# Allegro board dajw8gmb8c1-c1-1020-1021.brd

Outline 329.5 x 128.7 mm; copper layers: TOP, SGND, IN1, SVCC, IN2, IN3, SGND1, BOTTOM. Coordinates in mm from the lower left corner of the outline.

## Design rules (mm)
constraint set DEFAULT: min track width 0.102
net group DFP-S6W10-T123B: nets VCCSENSE VSSSENSE
net group T2B: nets USBPLLMON_N USBPLLMON_P
net group DFP-S4(4.5)W4(4.5)-T123B: nets HDMI_CLK_SINK HDMI_DAT_SINK HDMI_SCL HDMI_SDA
net group DFP-S5(4)W5(4: nets VMA_CLKN0 VMA_CLKN1 VMA_CLKP0 VMA_CLKP1 VMA_RDQS0 VMA_RDQS1 VMA_RDQS2 VMA_RDQS3 VMA_RDQS4 VMA_RDQS5 VMA_RDQS6 VMA_RDQS7 VMA_WDQS0 VMA_WDQS1 VMA_WDQS2 VMA_WDQS3 VMA_WDQS4 VMA_WDQS5 VMA_WDQS6 VMA_WDQS7
net group DFP-S5.5(5.5: nets EDP_AUXN EDP_AUXN_R EDP_AUXP EDP_AUXP_R EDP_TXN0 EDP_TXN0_RC EDP_TXN1 EDP_TXN1_RC EDP_TXP0 EDP_TXP0_RC EDP_TXP1 EDP_TXP1_RC INT_HDMI_TXCN INT_HDMI_TXCN_C INT_HDMI_TXCN_L INT_HDMI_TXCN_R INT_HDMI_TXCP INT_HDMI_TXCP_C INT_HDMI_TXCP_L INT_HDMI_TXCP_R INT_HDMI_TXN0 INT_HDMI_TXN0_C INT_HDMI_TXN0_L INT_HDMI_TXN0_R INT_HDMI_TXN1 INT_HDMI_TXN1_C INT_HDMI_TXN1_L INT_HDMI_TXN1_R INT_HDMI_TXN2 INT_HDMI_TXN2_C INT_HDMI_TXN2_L INT_HDMI_TXN2_R INT_HDMI_TXP0 INT_HDMI_TXP0_C INT_HDMI_TXP0_L INT_HDMI_TXP0_R INT_HDMI_TXP1 INT_HDMI_TXP1_C INT_HDMI_TXP1_L INT_HDMI_TXP1_R INT_HDMI_TXP2 INT_HDMI_TXP2_C INT_HDMI_TXP2_L INT_HDMI_TXP2_R M_B_CLKN0 M_B_CLKN1 M_B_CLKP0 M_B_CLKP1 M_B_DQSN0 M_B_DQSN1 M_B_DQSN2 M_B_DQSN3 M_B_DQSN4 M_B_DQSN5 M_B_DQSN6 M_B_DQSN7 M_B_DQSP0 M_B_DQSP1 M_B_DQSP2 M_B_DQSP3 M_B_DQSP4 M_B_DQSP5 M_B_DQSP6 M_B_DQSP7 PCIE_RXN2 PCIE_RXN2_C PCIE_RXN3 PCIE_RXN3_C PCIE_RXN4 PCIE_RXP2 PCIE_RXP2_C PCIE_RXP3 PCIE_RXP3_C PCIE_RXP4 PCIE_TXN2 PCIE_TXN2_C PCIE_TXN3 PCIE_TXN3_C PCIE_TXN4 PCIE_TXN4_C PCIE_TXP2 PCIE_TXP2_C PCIE_TXP3 PCIE_TXP3_C PCIE_TXP4 PCIE_TXP4_C PEG_RXN0 PEG_RXN0_C PEG_RXN1 PEG_RXN1_C PEG_RXN2 PEG_RXN2_C PEG_RXN3 PEG_RXN3_C PEG_RXP0 PEG_RXP0_C PEG_RXP1 PEG_RXP1_C PEG_RXP2 PEG_RXP2_C PEG_RXP3 PEG_RXP3_C PEG_TXN0 PEG_TXN0_C PEG_TXN1 PEG_TXN1_C PEG_TXN2 PEG_TXN2_C PEG_TXN3 PEG_TXN3_C PEG_TXP0 PEG_TXP0_C PEG_TXP1 PEG_TXP1_C PEG_TXP2 PEG_TXP2_C PEG_TXP3 PEG_TXP3_C SATA_RXN1 SATA_RXN1_C SATA_RXP1 SATA_RXP1_C SATA_TXN1 SATA_TXN1_C SATA_TXP1 SATA_TXP1_C USB3.0_RX1+ USB3.0_RX1- USB3.0_RX2+ USB3.0_RX2- USB3.0_RX3+ USB3.0_RX3- USB3.0_TX1+ USB3.0_TX1+_C USB3.0_TX1- USB3.0_TX1-_C USB3.0_TX2+ USB3.0_TX2+_C USB3.0_TX2- USB3.0_TX2-_C USB3.0_TX3+ USB3.0_TX3+_C USB3.0_TX3- USB3.0_TX3-_C USBP0+ USBP0+_C USBP0- USBP0-_C USBP1+ USBP1+_C USBP1+_R USBP1- USBP1-_C USBP1-_R USBP2+ USBP2+_C USBP2- USBP2-_C USBP3+ USBP3+_R_FT USBP3- USBP3-_R_FT USBP4+ USBP4+_CN USBP4- USBP4-_CN USBP5+ USBP5+_TOUCH USBP5- USBP5-_TOUCH USBP6+ USBP6- USBP7+ USBP7+_TSCR USBP7- USBP7-_TSCR
net group DFP-S5.5W4.5-TB: nets EDP_AUXN_C EDP_AUXP_C EDP_TXN0_C EDP_TXN0_R EDP_TXN0_RL EDP_TXN1_C EDP_TXN1_R EDP_TXN1_RL EDP_TXP0_C EDP_TXP0_R EDP_TXP0_RL EDP_TXP1_C EDP_TXP1_R EDP_TXP1_RL
net group DFP-S6(8: nets CLK_PCIE_CR_N CLK_PCIE_CR_P CLK_PCIE_LANN CLK_PCIE_LANP CLK_PCIE_VGAN CLK_PCIE_VGAP CLK_PCIE_WLANN CLK_PCIE_WLANP
net group DFP-S8W3.5-TB: nets LAN_MX0+ LAN_MX0- LAN_MX1+ LAN_MX1- LAN_MX2+ LAN_MX2- LAN_MX3+ LAN_MX3- MDI0+ MDI0- MDI1+ MDI1- MDI2+ MDI2- MDI3+ MDI3-
net group DFP-S8W4-TB: nets RTC_X1 RTC_X2 XTAL24_IN XTAL24_OUT
net group DFP-S10W4(3.5: nets SMB_CLK_ME1 SMB_DATA_ME1 SMB_PCH_CLK SMB_PCH_DAT SMBCLK SMBCLK0 SMBCLK1 SMBCLK3 SMBDAT0 SMBDAT1 SMBDAT3 SMBDATA
net group DFP-S10W10-T123B: nets REM_DIODE1_N REM_DIODE1_P VGA_THERMDN VGA_THERMDP
net group DFP-S20W40-T123B: nets L_SPK+ L_SPK- R_SPK+ R_SPK- SUB_OUT+ SUB_OUT+_L SUB_OUT- SUB_OUT-_L
net group DFP-S40W40-T123B: nets L_SPK+_R L_SPK-_R R_SPK+_R R_SPK-_R
net group T123B: nets +3.3V_RTC_LDO +CARD_3V3 +DCPSUSBYP +LCDVCC +LED_BL +RTC_1 +RTC_2 +RTC_CELL +V1.05DX_MODPHY +V1.05S_APLLOPI +V1.05S_ASATA3PLL +V1.05S_AUSB3PLL +V1.05S_AXCK_DCB +V1.05S_AXCK_LCPLL +V1.05S_VCCST +V3.3DX_CR +V3.3S_1.8S_LPSS_SDIO +VCCIO_OUT +VCCIOA_OUT +VCCRTCEXT CBN CBP COMBOJACK EARP_L EARP_L1 EARP_L2 EARP_R EARP_R1 EARP_R2 EDP_HPD EXT_MIC_2 EXT_MIC_L1 EXT_MIC_R EXT_MIC_R1 N130831290 N130831312 N130831363 N130831369 N130831515 RUN_ENABLE_1 RUN_ENABLE_2 RUN_ENABLE_3 SENSE_A SENSE_COMBO SM_RCOMP_0 SM_RCOMP_1 SM_RCOMP_2 SUS_ENABLE VREFOUT_AL
net group TB: nets EDP_COMP LAN_XTALI LAN_XTALO PCH_OPIRCOMP PCIE_IREF PROC_OPI_COMP SATA_IREF SATA_RCOMP USB_BIAS
net group W4(3.5: nets M_B_DQ0 M_B_DQ1 M_B_DQ2 M_B_DQ3 M_B_DQ4 M_B_DQ5 M_B_DQ6 M_B_DQ7 M_B_DQ8 M_B_DQ9 M_B_DQ10 M_B_DQ11 M_B_DQ12 M_B_DQ13 M_B_DQ14 M_B_DQ15 M_B_DQ16 M_B_DQ17 M_B_DQ18 M_B_DQ19 M_B_DQ20 M_B_DQ21 M_B_DQ22 M_B_DQ23 M_B_DQ24 M_B_DQ25 M_B_DQ26 M_B_DQ27 M_B_DQ28 M_B_DQ29 M_B_DQ30 M_B_DQ31 M_B_DQ32 M_B_DQ33 M_B_DQ34 M_B_DQ35 M_B_DQ36 M_B_DQ37 M_B_DQ38 M_B_DQ39 M_B_DQ40 M_B_DQ41 M_B_DQ42 M_B_DQ43 M_B_DQ44 M_B_DQ45 M_B_DQ46 M_B_DQ47 M_B_DQ48 M_B_DQ49 M_B_DQ50 M_B_DQ51 M_B_DQ52 M_B_DQ53 M_B_DQ54 M_B_DQ55 M_B_DQ56 M_B_DQ57 M_B_DQ58 M_B_DQ59 M_B_DQ60 M_B_DQ61 M_B_DQ62 M_B_DQ63
net group W4(3.5: nets 51622_ALERT# 51622_VCLK 51622_VDIO ACZ_SPKR AMP_BEEP AP_24M AP_I2S_DIN AP_I2S_DOUT BEEP BUF_PLT_RST# DDR3_DRAMRST# DP_UTIL DPWROK_R DSWVRMEN EC_PWROK EC_SPI_CLK EC_SPI_CS0# EC_SPI_CS# EC_SPI_DIN EC_SPI_DO EC_SPI_SI EC_SPI_SLK EC_SPI_SO EC_WAKE# H_CPU_SVIDALRT# H_CPUPWRGD H_PROCHOT# H_PROCHOT_EC HD_SDIN0 HDA_BEEP2 HDA_BITCLK HDA_BITCLK_R HDA_RST# HDA_RST#_R HDA_SDIN0 HDA_SDOUT HDA_SDOUT_R HDA_SYNC HDA_SYNC_R HSPI_CS# HWPG I2C_CK0 I2C_DA0 I2S_BCLK I2S_LRCK_FS IMVP7_PROCHOT# IRQ_SERIRQ LCD_PWM LPC_CLK_0 LPC_CLK_1 LPC_CLK_DEBUG LPC_CLK_EC LPC_LAD0 LPC_LAD1 LPC_LAD2 LPC_LAD3 LPC_LFRAME# N23727870 PCH_INTVRMEN PCH_SPI_CLK PCH_SPI_CS0# PCH_SPI_CS1# PCH_SPI_SI PCH_SPI_SO PCH_THRMTRIP# PCIE_EC_WAKE# PCIE_WAKE#_R PECI_EC PECI_EC_R PLTRST# RSMRST# RTC_RST# SD_CLK SIO_EXT_SCI# SIO_PWRBTN# SIO_RCIN# SIO_SLP_S3# SIO_SLP_S4# SIO_SLP_S5# SIO_WAKE_SCI# SLP_S0# SM_INTRUDER# SMC_EXTSMI_N SPI_CLK SPI_CS# SPI_SI SPI_SO SRTC_RST# SYS_PWROK SYS_SHDN# THERM_ALERT# THERM_STP# VCCST_PWRGD# VCCST_PWRGD_L VR_SVID_ALERT# VR_SVID_CLK VR_SVID_DATA
net group W4(4.5)-T123B: nets INT_HDMI_HP
net group W5(4.5: nets VMA_CMD0 VMA_CMD2 VMA_CMD3 VMA_CMD4 VMA_CMD5 VMA_CMD6 VMA_CMD7 VMA_CMD8 VMA_CMD9 VMA_CMD10 VMA_CMD11 VMA_CMD12 VMA_CMD13 VMA_CMD14 VMA_CMD15 VMA_CMD16 VMA_CMD18 VMA_CMD19 VMA_CMD20 VMA_CMD21 VMA_CMD22 VMA_CMD23 VMA_CMD24 VMA_CMD25 VMA_CMD26 VMA_CMD27 VMA_CMD28 VMA_CMD29 VMA_CMD30 VMA_DM0 VMA_DM1 VMA_DM2 VMA_DM3 VMA_DM4 VMA_DM5 VMA_DM6 VMA_DM7 VMA_DQ0 VMA_DQ1 VMA_DQ2 VMA_DQ3 VMA_DQ4 VMA_DQ5 VMA_DQ6 VMA_DQ7 VMA_DQ8 VMA_DQ9 VMA_DQ10 VMA_DQ11 VMA_DQ12 VMA_DQ13 VMA_DQ14 VMA_DQ15 VMA_DQ16 VMA_DQ17 VMA_DQ18 VMA_DQ19 VMA_DQ20 VMA_DQ21 VMA_DQ22 VMA_DQ23 VMA_DQ24 VMA_DQ25 VMA_DQ26 VMA_DQ27 VMA_DQ28 VMA_DQ29 VMA_DQ30 VMA_DQ31 VMA_DQ32 VMA_DQ33 VMA_DQ34 VMA_DQ35 VMA_DQ36 VMA_DQ37 VMA_DQ38 VMA_DQ39 VMA_DQ40 VMA_DQ41 VMA_DQ42 VMA_DQ43 VMA_DQ44 VMA_DQ45 VMA_DQ46 VMA_DQ47 VMA_DQ48 VMA_DQ49 VMA_DQ50 VMA_DQ51 VMA_DQ52 VMA_DQ53 VMA_DQ54 VMA_DQ55 VMA_DQ56 VMA_DQ57 VMA_DQ58 VMA_DQ59 VMA_DQ60 VMA_DQ61 VMA_DQ62 VMA_DQ63
net group W6.5(5.5: nets M_B_A0 M_B_A1 M_B_A2 M_B_A3 M_B_A4 M_B_A5 M_B_A6 M_B_A7 M_B_A8 M_B_A9 M_B_A10 M_B_A11 M_B_A12 M_B_A13 M_B_A14 M_B_A15 M_B_BS#0 M_B_BS#1 M_B_BS#2 M_B_CAS# M_B_CKE0 M_B_CKE1 M_B_CS#0 M_B_CS#1 M_B_RAS# M_B_WE#

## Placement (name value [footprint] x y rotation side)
C1  220P/50V_4  [CC0402]  173.87 126.07 180 top
C2  Dis@10U/6.3VS_6  [CC0603]  204.45 114.29 180 top
C3  Dis@10U/6.3VS_6  [CC0603]  204.45 112.89 180 top
C4  Dis@4.7U/6.3V_6  [CC0603]  193.91 112.64 270 top
C5  Dis@1U/6.3V_4  [CC0402]  224.77 112.38 90 top
C6  Dis@4.7U/6.3V_6  [CC0603]  204.45 111.62 0 top
C7  Dis@0.1U/16V_4  [CC0402]  180.45 110.73 0 top
C8  Dis@10U/6.3VS_6  [CC0603]  203.59 110.22 180 top
C9  Dis@10U/6.3V_6  [CC0603]  224.77 109.97 270 top
C10  Dis@0.1U/16V_4  [CC0402]  180.45 109.71 0 top
C11  10U/6.3V_6  [CC0603]  155.43 109.21 180 top
C12  10U/6.3V_6  [CC0603]  150.48 108.95 0 top
C13  0.1U/16V_4  [CC0402]  21.7 108.83 0 top
C14  Dis@0.1U/16V_4  [CC0402]  180.45 108.57 0 top
C15  Dis@4.7U/6.3V_6  [CC0603]  200.01 108.19 90 top
C16  Dis@10U/6.3VS_6  [CC0603]  201.28 108.19 270 top
C17  Dis@1U/6.3V_4  [CC0402]  198.48 107.94 270 top
C18  *1U/6.3V_4_NC  [CC0402]  155.3 107.81 0 top
C19  0.1U/16V_4  [CC0402]  150.35 107.68 180 top
C20  Dis@0.1U/16V_4  [CC0402]  180.45 107.56 0 top
C21  Dis@1U/6.3V_4  [CC0402]  224.77 107.56 270 top
C22  Dis@0.1U/16V_4  [CC0402]  193.02 107.43 0 top
C23  1U/6.3V_4  [CC0402]  16.37 106.92 0 top
C24  Dis@0.1U/16V_4  [CC0402]  180.45 106.41 0 top
C25  Dis@0.1U/16V_4  [CC0402]  180.45 105.4 0 top
C26  Dis@10U/6.3V_6  [CC0603]  210.29 105.14 270 top
C27  Dis@0.1U/16V_4  [CC0402]  180.45 104.25 0 top
C28  Dis@0.1U/16V_4  [CC0402]  180.45 103.24 0 top
C29  Dis@0.1U/16V_4  [CC0402]  210.29 102.73 90 top
C30  *Dis@0.1U/16V_4_NC  [CC0402]  180.96 101.59 90 top
C31  *10P/50V_4_NC  [CC0402]  14.97 101.08 180 top
C32  22P/50V_4  [CC0402]  20.3 101.08 0 top
C33  Dis@1U/6.3V_4  [CC0402]  210.29 100.57 270 top
C34  *10P/50V_4_NC  [CC0402]  14.97 99.81 180 top
C35  22P/50V_4  [CC0402]  20.3 99.81 0 top
C36  Dis@1U/6.3V_4  [CC0402]  195.44 99.17 180 top
C37  Dis@0.1U/16V_4  [CC0402]  224.77 99.17 270 top
C38  Dis@4.7U/6.3V_6  [CC0603]  197.98 99.05 180 top
C39  Dis@4.7U/6.3V_6  [CC0603]  180.2 98.79 0 top
C40  Dis@0.1U/16V_4  [CC0402]  189.39 98.69 270 top
C41  Dis@0.1U/16V_4  [CC0402]  190.43 98.67 90 top
C42  Dis@1U/6.3V_4  [CC0402]  191.52 98.67 90 top
C43  Dis@1U/6.3V_4  [CC0402]  193.78 98.67 270 top
C44  Dis@1U/6.3V_4  [CC0402]  192.64 98.64 90 top
C45  0.01U/16V_4  [CC0402]  19.03 98.06 90 top
C46  Dis@0.1U/16V_4  [CC0402]  188.22 98.36 90 top
C47  Dis@1U/6.3V_4  [CC0402]  210.29 98.28 270 top
C48  Dis@0.1U/16V_4  [CC0402]  195.44 98.13 0 top
C49  100P/50V_4  [CC0402]  131.05 98.03 270 top
C50  100P/50V_4  [CC0402]  133.59 97.9 270 top
C51  100P/50V_4  [CC0402]  138.67 97.9 270 top
C52  100P/50V_4  [CC0402]  141.08 97.9 270 top
C53  1U/6.3V_4  [CC0402]  152.31 97.52 0 top
C54  Dis@4.7U/6.3V_6  [CC0603]  180.2 97.52 0 top
C55  1U/6.3V_4  [CC0402]  149.49 97.47 0 top
C56  Dis@0.1U/16V_4  [CC0402]  198.1 97.42 270 top
C57  Dis@0.1U/16V_4  [CC0402]  199.17 97.42 90 top
C58  Dis@0.1U/16V_4  [CC0402]  196.48 96.89 0 top
C59  Dis@0.1U/16V_4  [CC0402]  194.29 96.86 180 top
C60  *Dis@0.1U/16V_4_NC  [CC0402]  178.29 96.76 90 top
C61  Dis@4.7U/6.3V_6  [CC0603]  189.01 96.68 180 top
C62  10U/6.3V_6  [CC0603]  126.73 96.14 180 top
C63  10U/6.3V_6  [CC0603]  144.51 96 180 top
C64  1U/6.3V_4  [CC0402]  153.09 95.95 180 top
C65  Dis@0.1U/16V_4  [CC0402]  191.65 95.9 0 top
C66  1U/6.3V_4  [CC0402]  150.86 95.87 180 top
C67  1U/6.3V_4  [CC0402]  148.57 95.74 90 top
C68  Dis@4.7U/6.3V_6  [CC0603]  197.37 95.67 0 top
C69  10U/6.3V_6  [CC0603]  128.63 95.51 90 top
C70  10U/6.3V_6  [CC0603]  131.17 95.51 90 top
C71  10U/6.3V_6  [CC0603]  132.44 95.51 90 top
C72  10U/6.3V_6  [CC0603]  133.71 95.51 90 top
C73  10U/6.3V_6  [CC0603]  140.06 95.51 90 top
C74  10U/6.3V_6  [CC0603]  141.33 95.51 90 top
C75  10U/6.3V_6  [CC0603]  129.9 95.49 90 top
C76  10U/6.3V_6  [CC0603]  134.98 95.49 90 top
C77  10U/6.3V_6  [CC0603]  136.25 95.49 90 top
C78  10U/6.3V_6  [CC0603]  137.52 95.49 90 top
C79  10U/6.3V_6  [CC0603]  138.79 95.49 90 top
C80  Dis@0.1U/16V_4  [CC0402]  194.24 95.44 180 top
C81  Dis@0.1U/16V_4  [CC0402]  199.17 95.36 270 top
C82  10U/6.3V_6  [CC0603]  126.73 94.87 180 top
C83  10U/6.3V_6  [CC0603]  143.24 94.73 0 top
C84  1U/6.3V_4  [CC0402]  153.02 94.47 180 top
C85  Dis@4.7U/6.3V_6  [CC0603]  188.78 94.37 180 top
C86  Dis@4.7U/6.3V_6  [CC0603]  191.42 94.37 0 top
C87  0.01U/16V_4  [CC0402]  22.33 93.79 180 top
C88  1U/6.3V_4  [CC0402]  155.05 94.22 270 top
C89  Dis@0.1U/16V_4  [CC0402]  197.49 94.19 0 top
C90  *4.7U/6.3V_6_NC  [CC0603]  19.9 93.66 180 top
C91  0.1U/16V_4  [CC0402]  151.49 93.97 270 top
C92  10U/6.3V_6  [CC0603]  149.59 93.59 180 top
C93  Dis@4.7U/6.3V_6  [CC0603]  194.52 93.59 180 top
C94  10U/6.3V_6  [CC0603]  143.24 93.46 0 top
C95  1U/6.3V_4  [CC0402]  153.02 93.46 180 top
C96  Dis@1U/6.3V_4  [CC0402]  199.17 93.31 270 top
C97  10U/6.3V_6  [CC0603]  127.36 93.2 180 top
C98  Dis@1U/6.3V_4  [CC0402]  224.77 93.08 270 top
C99  Dis@0.1U/16V_4  [CC0402]  188.78 92.87 180 top
C100  Dis@0.1U/16V_4  [CC0402]  197.57 92.87 0 top
C101  Dis@4.7U/6.3V_6  [CC0603]  191.35 92.75 0 top
C102  1U/6.3V_4  [CC0402]  154.54 92.44 0 top
C103  Dis@0.1U/16V_4  [CC0402]  179.69 92.44 90 top
C104  Dis@0.1U/16V_4  [CC0402]  180.83 92.44 90 top
C105  10U/6.3V_6  [CC0603]  149.59 92.32 0 top
C106  10U/6.3V_6  [CC0603]  143.24 92.19 0 top
C107  10U/6.3V_6  [CC0603]  127.36 91.93 180 top
C108  1U/6.3V_4  [CC0402]  152.51 91.81 0 top
C109  Dis@2.2U/6.3V_6  [CC0603]  198.15 91.71 180 top
C110  Dis@4.7U/6.3V_6  [CC0603]  177.15 91.68 90 top
C111  Dis@10U/6.3VS_6  [CC0603]  178.42 91.68 90 top
C112  Dis@4.7U/6.3V_6  [CC0603]  194.52 91.48 180 top
C113  Dis@4.7U/6.3V_6  [CC0603]  189.01 91.38 180 top
C114  *2200P/50V_4_NC  [CC0402]  137.4 91.31 270 top
C115  1U/6.3V_4  [CC0402]  154.54 91.3 180 top
C116  0.1U/16V_4  [CC0402]  166.23 91.17 0 top
C117  10U/6.3V_6  [CC0603]  172.58 91.17 0 top
C118  10U/6.3V_6  [CC0603]  149.59 91.05 0 top
C119  10U/6.3V_6  [CC0603]  143.24 90.92 0 top
C120  0.1U/16V_4  [CC0402]  168.38 90.79 270 top
C121  1U/6.3V_4  [CC0402]  169.4 90.79 270 top
C122  1U/6.3V_4  [CC0402]  170.54 90.79 270 top
C123  10U/6.3V_6  [CC0603]  127.36 90.68 180 top
C124  Dis@4.7U/6.3V_6  [CC0603]  198.18 90.51 180 top
C125  Dis@0.1U/16V_4  [CC0402]  191.09 90.08 270 top
C126  0.1U/16V_4  [CC0402]  146.29 90.03 270 top
C127  1U/6.3V_4  [CC0402]  147.3 90.03 270 top
C128  10U/6.3V_6  [CC0603]  149.59 89.78 180 top
C129  10U/6.3V_6  [CC0603]  144.38 89.65 180 top
C130  1U/6.3V_4  [CC0402]  152.51 89.65 0 top
C131  0.1U/16V_4  [CC0402]  155.05 89.65 90 top
C132  10U/6.3V_6  [CC0603]  127.36 89.41 180 top
C133  Dis@10U/6.3V_6  [CC0603]  194.17 89.14 90 top
C134  Dis@10U/6.3V_6  [CC0603]  193 89.11 90 top
C135  Dis@0.1U/16V_4  [CC0402]  188.53 89.04 90 top
C136  Dis@0.1U/16V_4  [CC0402]  189.67 89.04 90 top
C137  Dis@0.1U/16V_4  [CC0402]  180.83 89.01 270 top
C138  Dis@0.1U/16V_4  [CC0402]  195.56 88.89 270 top
C139  Dis@10U/6.3VS_6  [CC0603]  179.69 88.76 270 top
C140  Dis@0.1U/16V_4  [CC0402]  196.83 88.76 270 top
C141  Dis@1U/6.3V_4  [CC0402]  197.85 88.76 90 top
C142  Dis@0.1U/16V_4  [CC0402]  198.86 88.76 90 top
C143  1U/6.3V_4  [CC0402]  137.65 88.51 90 top
C144  1U/6.3V_4  [CC0402]  139.43 88.51 90 top
C145  0.1U/16V_4  [CC0402]  140.83 88.51 270 top
C146  0.1U/16V_4  [CC0402]  142.22 88.51 270 top
C147  Dis@2200P/50V_4  [CC0402]  191.22 88.33 0 top
C148  10U/6.3V_6  [CC0603]  127.36 88.14 180 top
C149  1U/6.3V_4  [CC0402]  147.56 87.87 270 top
C150  1U/6.3V_4  [CC0402]  148.83 87.87 270 top
C151  1U/6.3V_4  [CC0402]  149.97 87.87 270 top
C152  1U/6.3V_4  [CC0402]  150.99 87.87 270 top
C153  1U/6.3V_4  [CC0402]  152 87.87 270 top
C154  1U/6.3V_4  [CC0402]  153.02 87.62 270 top
C155  0.1U/16V_4  [CC0402]  154.11 87.62 90 top
C156  1U/6.3V_4  [CC0402]  155.15 87.62 90 top
C157  Dis@1U/6.3V_4  [CC0402]  225.92 86.98 0 top
C158  10U/6.3V_6  [CC0603]  127.36 86.87 180 top
C159  Dis@1U/6.3V_4  [CC0402]  210.29 86.73 270 top
C160  Dis@0.1U/16V_4  [CC0402]  226.04 85.97 180 top
C161  Dis@10U/6.3V_6  [CC0603]  226.3 84.82 180 top
C162  Dis@1U/6.3V_4  [CC0402]  210.29 84.57 90 top
C163  Dis@4.7U/6.3V_6  [CC0603]  180.2 84.31 0 top
C164  Dis@10U/6.3V_6  [CC0603]  226.3 83.55 180 top
C165  Dis@2.2U/6.3V_6  [CC0603]  180.2 83.04 0 top
C166  0.1U/16V_4  [CC0402]  17.41 62.85 180 top
C167  150P/50V_4  [CC0402]  17.41 61.84 180 top
C168  1U/6.3V_4  [CC0402]  173.34 80.38 180 top
C169  Dis@10U/6.3VS_6  [CC0603]  182.23 80 0 top
C170  Dis@0.1U/16V_4  [CC0402]  226.04 79.23 180 top
C171  0.1U/16V_4  [CC0402]  21.85 79.03 0 top
C172  Dis@4.7U/6.3V_6  [CC0603]  182.23 78.73 0 top
C173  Dis@1U/6.3V_4  [CC0402]  226.04 78.22 0 top
C174  0.1U/16V_4  [CC0402]  21.85 77.89 0 top
C175  Dis@4.7U/6.3V_6  [CC0603]  184.39 77.2 180 top
C176  Dis@1U/6.3V_4  [CC0402]  226.04 77.2 0 top
C177  Dis@1U/6.3V_4  [CC0402]  210.29 76.95 270 top
C178  0.1U/16V_4  [CC0402]  305.93 76.44 270 top
C179  0.1U/16V_4  [CC0402]  306.94 76.44 270 top
C180  0.1U/16V_4  [CC0402]  308.08 76.44 270 top
C181  0.1U/16V_4  [CC0402]  309.1 76.44 270 top
C182  0.1U/16V_4  [CC0402]  310.24 76.44 270 top
C183  0.1U/16V_4  [CC0402]  311.26 76.44 270 top
C184  0.1U/16V_4  [CC0402]  312.4 76.44 270 top
C185  0.1U/16V_4  [CC0402]  313.42 76.44 270 top
C186  Dis@4.7U/6.3V_6  [CC0603]  193.61 76.31 180 top
C187  Dis@4.7U/6.3V_6  [CC0603]  184.39 75.93 180 top
C188  Dis@0.1U/16V_4  [CC0402]  226.68 75.42 270 top
C189  Dis@4.7U/6.3V_6  [CC0603]  193.63 75.02 180 top
C190  1U/6.3V_4  [CC0402]  155.56 74.55 270 top
C191  2200P/50V_4  [CC0402]  114.41 73.77 0 top
C192  Dis@4.7U/6.3V_6  [CC0603]  193.66 73.77 180 top
C193  *0.1U/16V_4_NC  [CC0402]  174.73 73.14 180 top
C194  0.1U/16V_4  [CC0402]  116.7 72 90 top
C195  0.1U/16V_4  [CC0402]  156.7 70.22 270 top
C196  1U/6.3V_4  [CC0402]  157.84 70.22 90 top
C197  0.1U/16V_4  [CC0402]  125.66 113.45 180 top
C198  0.1U/16V_4  [CC0402]  308.16 67.32 180 top
C199  Dis@0.1U/16V_4  [CC0402]  185.4 67.04 270 top
C200  0.1U/16V_4  [CC0402]  308.16 66.31 180 top
C201  150P/50V_4  [CC0402]  312.4 64.88 90 top
C202  0.1U/16V_4  [CC0402]  313.42 64.88 90 top
C203  0.1U/16V_4  [CC0402]  17.08 82 180 top
C204  150P/50V_4  [CC0402]  17.08 80.99 180 top
C205  0.1U/16V_4  [CC0402]  20.94 61 0 top
C206  0.1U/16V_4  [CC0402]  20.94 59.98 0 top
C207  0.1U/16V_4  [CC0402]  301.1 56.5 90 top
C208  *4.7U/6.3V_6_NC  [CC0603]  291.45 53 90 top
C209  0.1U/16V_4  [CC0402]  290.3 52.82 90 top
C210  0.1U/16V_4  [CC0402]  287.64 52.69 180 top
C211  *0.1U/16V_4_NC  [CC0402]  295.38 52.31 90 top
C212  0.1U/16V_4  [CC0402]  110.47 51.68 90 top
C213  0.1U/16V_4  [CC0402]  287.64 51.68 180 top
C214  0.1U/16V_4  [CC0402]  284.72 49.52 180 top
C215  0.022U/16V_4  [CC0402]  113.39 48.75 0 top
C216  0.1U/16V_4  [CC0402]  284.72 48.5 180 top
C217  0.1U/16V_4  [CC0402]  177.4 47.61 270 top
C218  2.2U/6.3V_6  [CC0603]  178.54 47.61 270 top
C219  0.01U/16V_4  [CC0402]  268.46 38.85 270 bottom
C220  *0.1U/16V_4_NC  [CC0402]  294.98 45.63 180 top
C221  0.01U/16V_4  [CC0402]  113.39 46.72 0 top
C222  1U/6.3V_4  [CC0402]  284.08 46.72 270 top
C223  0.1U/16V_4  [CC0402]  285.22 46.72 270 top
C224  1U/6.3V_4  [CC0402]  272.14 39.48 270 bottom
C225  0.01U/16V_4  [CC0402]  270.14 36.94 90 top
C226  4.7U/6.3VS_6  [CC0603]  140.19 44.94 270 top
C227  4.7U/6.3VS_6  [CC0603]  143.75 44.94 270 top
C228  10U/6.3V_6  [CC0603]  147.43 44.94 90 top
C229  10U/6.3V_6  [CC0603]  150.99 44.94 90 top
C230  10U/6.3V_6  [CC0603]  154.54 44.94 270 top
C231  1U/6.3V_4  [CC0402]  145.65 44.82 90 top
C232  1U/6.3V_4  [CC0402]  149.21 44.82 90 top
C233  0.01U/16V_4  [CC0402]  113.39 44.69 0 top
C234  1U/6.3V_4  [CC0402]  271.15 36.94 90 top
C236  0.1U/16V_4  [CC0402]  283.95 44.31 180 top
C237  0.1U/16V_4  [CC0402]  293.23 44.31 180 top
C238  1U/6.3V_4  [CC0402]  269.1 36.31 90 top
C239  10P/50V_4  [CC0402]  288.65 44.18 0 top
C240  10P/50V_4  [CC0402]  290.81 44.18 180 top
C241  1U/6.3V_4  [CC0402]  179.69 44.06 0 top
C242  0.1U/16V_4  [CC0402]  301.23 43.8 270 top
C243  0.1U/16V_4  [CC0402]  113.39 43.67 0 top
C244  10U/6.3V_6  [CC0603]  298.69 43.67 90 top
C245  10U/6.3V_6  [CC0603]  299.96 43.67 90 top
C246  1U/6.3V_4  [CC0402]  263.25 39.74 0 top
C248  1U/6.3V_4  [CC0402]  179.69 43.04 0 top
C249  *4.7U/6.3V_6_NC  [CC0603]  293.48 43.04 180 top
C250  1U/6.3V_4  [CC0402]  228.2 42.91 0 top
C251  4.7U/6.3V_6  [CC0603]  283.7 42.91 0 top
C252  2.2U/6.3V_6  [CC0603]  113.39 42.53 0 top
C253  1U/6.3V_4  [CC0402]  59.16 42.28 0 top
C254  4.7U/6.3V_6  [CC0603]  62.21 42.15 180 top
C255  10U/6.3V_6  [CC0603]  306.81 42.15 0 top
C256  *0.1U/16V_4_NC  [CC0402]  219.64 41.46 0 top
C257  0.1U/16V_4  [CC0402]  308.85 42.02 270 top
C258  4.7U/6.3V_6  [CC0603]  54.59 41.77 180 top
C259  0.1U/16V_4  [CC0402]  309.99 41.64 270 top
C260  0.1U/16V_4  [CC0402]  298.94 40.75 90 top
C261  0.1U/16V_4  [CC0402]  303.13 40.75 270 top
C262  0.1U/16V_4  [CC0402]  62.34 40.63 180 top
C263  10U/6.3V_6  [CC0603]  301.35 40.88 90 top
C264  1U/6.3V_4  [CC0402]  268.08 36.31 270 top
C265  0.1U/16V_4  [CC0402]  67.8 41.52 180 top
C266  0.01U/16V_4  [CC0402]  267.06 36.31 270 top
C268  0.1U/16V_4  [CC0402]  53.07 39.49 0 top
C269  100P/50V_4  [CC0402]  183.24 39.36 0 top
C270  *Clamp-Diode_NC  [CC0402]  317.46 39.05 270 top
C272  10U/6.3V_6  [CC0603]  62.72 38.59 180 top
C273  10U/6.3V_6  [CC0603]  300.08 38.59 180 top
C274  2.2U/6.3V_6  [CC0603]  312.91 38.59 180 top
C276  *10P/50V_4_NC  [CC0402]  297.67 38.47 0 top
C277  1U/6.3V_4  [CC0402]  180.96 38.34 180 top
C278  1000P/50V_4  [CC0402]  321.8 38.34 270 top
C279  10U/6.3V_6  [CC0603]  34.5 38.11 270 top
C280  0.1U/16V_4  [CC0402]  254.29 38.37 270 top
C281  0.1U/16V_4  [CC0402]  255.3 38.37 270 top
C282  0.1U/16V_4  [CC0402]  257.03 38.34 270 top
C283  0.1U/16V_4  [CC0402]  258.05 38.34 270 top
C284  100P/50V_4  [CC0402]  315.7 37.58 270 top
C285  0.1U/16V_4  [CC0402]  62.46 37.45 180 top
C287  1U/6.3V_4  [CC0402]  180.96 37.32 180 top
C289  2.2U/6.3V_6  [CC0603]  312.91 37.07 0 top
C292  2.2U/6.3V_6  [CC0603]  155.68 36.82 270 top
C293  1U/6.3V_4  [CC0402]  145.91 36.56 270 top
C294  1U/6.3V_4  [CC0402]  149.59 36.56 270 top
C295  0.1U/16V_4  [CC0402]  156.83 36.56 270 top
C296  0.01U/16V_4  [CC0402]  157.84 36.56 270 top
C297  0.01U/16V_4  [CC0402]  159.88 36.56 270 top
C298  0.022U/16V_4  [CC0402]  161.91 36.56 270 top
C299  0.1U/16V_4  [CC0402]  62.46 36.44 180 top
C300  4.7U/6.3VS_6  [CC0603]  140.44 36.44 270 top
C301  4.7U/6.3VS_6  [CC0603]  144.13 36.44 90 top
C302  4.7U/6.3VS_6  [CC0603]  147.68 36.44 90 top
C303  4.7U/6.3VS_6  [CC0603]  153.14 36.44 90 top
C304  0.1U/16V_4  [CC0402]  299.82 36.45 180 top
C305  4.7U/6.3VS_6  [CC0603]  180.83 36.18 0 top
C306  1U/6.3V_4  [CC0402]  271 39.48 270 bottom
C307  1U/6.3V_4  [CC0402]  269.73 39.36 270 bottom
C308  1U/6.3V_4  [CC0402]  267.44 38.85 270 bottom
C309  0.1U/16V_4  [CC0402]  262.14 33.41 180 top
C314  *10P/50V_4_NC  [CC0402]  297.67 35.47 0 top
C315  *4.7U/6.3V_6_NC  [CC0603]  62.72 35.29 180 top
C316  0.1U/16V_4  [CC0402]  231.25 35.04 270 top
C317  10U/6.3V_6  [CC0603]  180.83 34.91 0 top
C318  0.1U/16V_4  [CC0402]  210.8 34.91 180 top
C319  0.1U/16V_4  [CC0402]  228.07 34.91 90 top
C320  0.1U/16V_4  [CC0402]  262.14 32.27 180 top
C321  *10P/50V_4_NC  [CC0402]  299.82 34.42 0 top
C322  *10P/50V_4_NC  [CC0402]  297.66 34.16 0 top
C323  4.7U/6.3V_6  [CC0603]  312.91 33.77 0 top
C324  0.1U/16V_4  [CC0402]  56.88 32.88 90 top
C325  0.1U/16V_4  [CC0402]  57.89 32.88 90 top
C326  4.7U/6.3V_6  [CC0603]  312.91 32.5 180 top
C327  0.1U/16V_4  [CC0402]  299.83 31.99 0 top
C328  0.1U/16V_4  [CC0402]  59.29 31.86 90 top
C329  0.1U/16V_4  [CC0402]  60.31 31.86 90 top
C330  2.2U/6.3V_6  [CC0603]  297.42 31.86 0 top
C332  0.1U/16V_4  [CC0402]  312.15 31.23 180 top
C333  0.1U/16V_4  [CC0402]  65.01 31.1 0 top
C335  *10P/50V_4_NC  [CC0402]  299.83 30.97 180 top
C337  100P/50V_4  [CC0402]  315.58 30.59 0 top
C338  2.2U/6.3V_6  [CC0603]  312.02 30.09 0 top
C341  *Clamp-Diode_NC  [CC0402]  315.58 29.58 0 top
C342  *0.1U/25V_6_NC  [CC0603]  87.16 29.2 90 top
C343  10U/6.3V_6  [CC0603]  285.86 28.56 90 top
C344  10P/50V_4  [CC0402]  191.63 28.69 90 top
C345  1U/6.3V_4  [CC0402]  301.35 28.56 270 top
C346  0.1U/16V_4  [CC0402]  76.94 28.43 0 top
C349  0.1U/16V_4  [CC0402]  202.29 28.18 90 top
C350  1U/6.3V_4  [CC0402]  287.13 28.2 90 top
C351  0.1U/16V_4  [CC0402]  288.27 28.2 270 top
C352  1U/25V_6  [CC0603]  312.66 28.18 90 top
C353  *100P/50V_4_NC  [CC0402]  314.94 28.05 270 top
C354  1U/6.3V_4  [CC0402]  299.83 27.93 180 top
C355  10U/6.3V_6  [CC0603]  307.96 27.93 90 top
C356  0.1U/16V_4  [CC0402]  76.94 27.42 0 top
C358  0.015U/16V_4  [CC0402]  296.96 27.16 0 top
C359  *10P/50V_4_NC  [CC0402]  305.67 26.91 0 top
C360  *Clamp-Diode_NC  [CC0402]  316.06 27.16 90 top
C361  10P/50V_4  [CC0402]  191.63 26.66 270 top
C362  0.01U/16V_4  [CC0402]  268.08 26.28 90 top
C363  0.01U/16V_4  [CC0402]  269.1 26.28 90 top
C364  0.01U/16V_4  [CC0402]  271.51 26.28 90 top
C365  0.01U/16V_4  [CC0402]  272.52 26.28 90 top
C369  220P/50V_4  [CC0402]  209.28 25.26 90 top
C370  220P/50V_4  [CC0402]  210.29 25.26 90 top
C371  220P/50V_4  [CC0402]  211.31 25.26 90 top
C372  220P/50V_4  [CC0402]  212.33 25.26 90 top
C373  220P/50V_4  [CC0402]  213.34 25.26 90 top
C374  220P/50V_4  [CC0402]  214.36 25.26 90 top
C375  220P/50V_4  [CC0402]  215.37 25.26 90 top
C376  220P/50V_4  [CC0402]  216.39 25.26 90 top
C377  220P/50V_4  [CC0402]  217.41 25.26 90 top
C378  220P/50V_4  [CC0402]  218.42 25.26 90 top
C379  220P/50V_4  [CC0402]  219.44 25.26 90 top
C380  220P/50V_4  [CC0402]  220.45 25.26 90 top
C381  220P/50V_4  [CC0402]  221.47 25.26 90 top
C382  220P/50V_4  [CC0402]  222.49 25.26 90 top
C383  220P/50V_4  [CC0402]  223.5 25.26 90 top
C384  220P/50V_4  [CC0402]  224.52 25.26 90 top
C385  220P/50V_4  [CC0402]  225.53 25.26 90 top
C386  220P/50V_4  [CC0402]  226.55 25.26 90 top
C387  220P/50V_4  [CC0402]  227.57 25.26 90 top
C388  220P/50V_4  [CC0402]  228.58 25.26 90 top
C389  220P/50V_4  [CC0402]  229.6 25.26 90 top
C390  220P/50V_4  [CC0402]  230.61 25.26 90 top
C391  220P/50V_4  [CC0402]  231.63 25.26 90 top
C392  220P/50V_4  [CC0402]  232.65 25.26 90 top
C393  0.1U/16V_4  [CC0402]  282.84 32.04 90 top
C394  0.015U/16V_4  [CC0402]  295.77 24.62 0 top
C395  4.7U/6.3V_6  [CC0603]  72.25 27.42 180 top
C397  *0.1U/16V_4_NC  [CC0402]  189.85 22.47 180 top
C398  0.1U/16V_4  [CC0402]  191.88 22.47 0 top
C399  0.1U/16V_4  [CC0402]  72.37 26.15 180 top
C401  1U/6.3V_4  [CC0402]  19.03 6.72 90 top
C402  Dis@0.1U/16V_4  [CC0402]  177.4 114.29 0 bottom
C403  Dis@0.1U/16V_4  [CC0402]  177.4 113.27 0 bottom
C404  Dis@0.1U/16V_4  [CC0402]  177.4 112.25 0 bottom
C405  Dis@0.1U/16V_4  [CC0402]  177.4 111.24 0 bottom
C406  Dis@4.7U/6.3V_6  [CC0603]  204.58 111.11 0 bottom
C407  Dis@10U/6.3V_6  [CC0603]  224.77 110.35 270 bottom
C408  Dis@0.1U/16V_4  [CC0402]  177.4 110.22 0 bottom
C409  Dis@4.7U/6.3V_6  [CC0603]  204.58 109.59 0 bottom
C410  Dis@0.1U/16V_4  [CC0402]  177.4 109.21 0 bottom
C411  10U/6.3V_6  [CC0603]  148.95 108.83 90 bottom
C412  Dis@4.7U/6.3V_6  [CC0603]  204.58 108.32 0 bottom
C413  Dis@0.1U/16V_4  [CC0402]  177.4 108.19 0 bottom
C414  Dis@0.1U/16V_4  [CC0402]  224.77 107.94 90 bottom
C415  10U/6.3V_6  [CC0603]  159.62 107.3 0 bottom
C416  Dis@0.1U/16V_4  [CC0402]  177.4 107.17 0 bottom
C417  0.1U/16V_4  [CC0402]  151.32 106.04 0 bottom
C418  1U/6.3V_4  [CC0402]  149.29 106.04 180 bottom
C419  0.1U/16V_4  [CC0402]  159.88 106.03 180 bottom
C420  Dis@0.1U/16V_4  [CC0402]  224.77 105.9 270 bottom
C421  10U/6.3V_6  [CC0603]  152.97 105.78 90 bottom
C422  10P/50V_4  [CC0402]  143.7 105.15 180 bottom
C423  10P/50V_4  [CC0402]  139.63 105.15 0 bottom
C424  1U/6.3V_4  [CC0402]  151.32 105.02 0 bottom
C425  0.1U/16V_4  [CC0402]  149.29 105.02 180 bottom
C426  1U/6.3V_4  [CC0402]  159.88 105.02 180 bottom
C427  Dis@0.1U/16V_4  [CC0402]  210.29 102.86 270 bottom
C428  Dis@0.1U/16V_4  [CC0402]  210.29 98.54 90 bottom
C429  Dis@1U/6.3V_4  [CC0402]  224.77 97.65 90 bottom
C430  Dis@1U/6.3V_4  [CC0402]  210.29 96.38 270 bottom
C431  Dis@1U/6.3V_4  [CC0402]  224.77 95.62 270 bottom
C432  Dis@1U/6.3V_4  [CC0402]  226.04 86.73 0 bottom
C433  Dis@0.1U/16V_4  [CC0402]  226.04 85.71 180 bottom
C434  Dis@1U/6.3V_4  [CC0402]  210.29 85.58 90 bottom
C435  0.01U/16V_4  [CC0402]  307.83 85.46 180 bottom
C436  0.1U/16V_4  [CC0402]  312.28 85.2 0 bottom
C437  0.1U/16V_4  [CC0402]  314.13 84.54 270 bottom
C438  0.1U/16V_4  [CC0402]  307.83 84.44 180 bottom
C439  0.1U/16V_4  [CC0402]  312.5 84.19 0 bottom
C440  Dis@0.1U/16V_4  [CC0402]  225.53 82.92 90 bottom
C441  10U/6.3V_8  [CC0805]  17.1 59.88 90 bottom
C442  0.01U/16V_4  [CC0402]  312.5 81.01 0 bottom
C443  0.01U/16V_4  [CC0402]  307.83 80.89 180 bottom
C444  0.1U/16V_4  [CC0402]  312.5 79.92 0 bottom
C445  Dis@10P/50V_4  [CC0402]  191.63 79.74 0 bottom
C446  Dis@10P/50V_4  [CC0402]  189.59 79.74 180 bottom
C447  Dis@0.1U/16V_4  [CC0402]  210.29 79.23 270 bottom
C448  *Dis@1000P/50V_4_NC  [CC0402]  184.89 76.39 180 bottom
C449  Dis@220U/2.5V_3528  [CC3528]  227.82 75.81 0 bottom
C450  1U/6.3V_4  [CC0402]  160.51 75.3 270 bottom
C451  10U/6.3V_6  [CC0603]  134.05 75.05 90 bottom
C452  10U/6.3V_6  [CC0603]  132.78 75.05 90 bottom
C453  10U/6.3V_6  [CC0603]  131.25 75.05 90 bottom
C454  10U/6.3V_6  [CC0603]  129.98 75.05 90 bottom
C455  10U/6.3V_6  [CC0603]  136.63 75.04 90 bottom
C456  10U/6.3V_6  [CC0603]  135.36 75.04 90 bottom
C457  15P/50V/_4  [CC0402]  166.48 74.92 0 bottom
C458  15P/50V/_4  [CC0402]  164.32 74.92 180 bottom
C459  Dis@10U/6.3V_6  [CC0603]  226.17 73.65 0 bottom
C460  *33P/50V/NPO_4_NC  [CC0402]  156.19 73.65 180 bottom
C461  Dis@1000P/50V_4  [CC0402]  178.54 73.14 0 bottom
C462  *Dis@1000P/50V_4_NC  [CC0402]  185.07 71.69 90 bottom
C463  Dis@10U/6.3V_8  [CC0805]  196.73 70.19 0 bottom
C464  Dis@4.7U/6.3V_6  [CC0603]  187.56 70.09 180 bottom
C465  0.1U/16V_4  [CC0402]  302.5 66.15 0 bottom
C466  10U/6.3V_8  [CC0805]  312.78 65.01 90 bottom
C467  *10U/6.3V_8_NC  [CC0805]  301.61 64.38 0 bottom
C468  *10U/6.3V_8_NC  [CC0805]  23.73 62.47 180 bottom
C469  10P/3KV_1808  [CC1808]  305.42 61.58 0 bottom
C470  10U/6.3V_8  [CC0805]  17.15 81.14 270 bottom
C471  0.1U/16V_4  [CC0402]  22.84 60.18 90 bottom
C472  4.7U/6.3V_6  [CC0603]  237.85 59.42 270 bottom
C473  0.1U/16V_4  [CC0402]  239 59.17 90 bottom
C474  0.1U/16V_4  [CC0402]  28.61 57.64 90 bottom
C475  10U/6.3V/X5R_8  [CC0805]  26.83 60.54 90 bottom
C476  0.1U/16V_4  [CC0402]  103.11 52.31 270 bottom
C477  4.7U/6.3V_6  [CC0603]  104.38 52.18 90 bottom
C478  4.7U/6.3V_6  [CC0603]  283.95 49.39 180 bottom
C479  0.1U/16V_4  [CC0402]  291.32 49.01 0 bottom
C480  0.1U/16V_4  [CC0402]  291.32 47.74 0 bottom
C481  0.1U/16V_4  [CC0402]  281.41 47.48 180 bottom
C482  0.1U/16V_4  [CC0402]  281.41 48.5 0 bottom
C483  0.1U/16V_4  [CC0402]  291.32 46.6 0 bottom
C484  *0.1U/16V_4_NC  [CC0402]  241.29 46.21 90 bottom
C486  0.1U/16V_4  [CC0402]  254.87 41.77 180 bottom
C487  *0.1U/16V_4_NC  [CC0402]  192.01 42.53 90 bottom
C488  0.1U/16V_4  [CC0402]  311.13 41.64 270 bottom
C490  0.1U/16V_4  [CC0402]  275.7 46.72 180 top
C491  0.1U/16V_4  [CC0402]  238.62 40.5 270 bottom
C492  0.1U/16V_4  [CC0402]  312.15 39.48 270 bottom
C493  0.1U/16V_4  [CC0402]  311.13 39.48 270 bottom
C494  2.2U/6.3V_6  [CC0603]  295.56 40.17 0 bottom
C495  0.1U/16V_4  [CC0402]  275.19 40.37 180 top
C496  0.1U/25V/X7R_6  [CC0603]  274.94 38.21 180 top
C497  0.1U/16V_4  [CC0402]  34.5 38.19 270 bottom
C498  680P/50V_4  [CC0402]  295.77 38.77 0 bottom
C499  0.1U/16V_4  [CC0402]  275.19 39.36 180 top
C500  10U/6.3V_6  [CC0603]  312.4 37.07 270 bottom
C501  10U/6.3V_6  [CC0603]  311.13 37.07 90 bottom
C502  1U/6.3V_4  [CC0402]  214.74 36.69 0 bottom
C503  680P/50V_4  [CC0402]  295.77 36.05 0 bottom
C504  0.1U/16V_4  [CC0402]  216.39 36.05 90 bottom
C505  680P/50V_4  [CC0402]  295.64 33.39 0 bottom
C506  0.1U/16V_4  [CC0402]  311.76 31.52 180 bottom
C507  680P/50V_4  [CC0402]  295.77 31.74 0 bottom
C508  *10U/6.3V_6_NC  [CC0603]  288.53 31.23 0 bottom
C509  0.1U/25V/X7R_6  [CC0603]  285.43 27.88 90 bottom
C510  10U/6.3V_6  [CC0603]  312.39 32.77 180 bottom
C511  0.1U/16V_4  [CC0402]  216.01 30.72 180 bottom
C512  1000P/50V_4  [CC0402]  295.77 30.34 180 bottom
C513  0.1U/16V_4  [CC0402]  206.87 30.09 180 bottom
C514  4.7U/6.3V_6  [CC0603]  288.53 29.96 0 bottom
C515  0.1U/25VX7R_6  [CC0603]  286.62 27.88 90 bottom
C516  0.1U/16V_4  [CC0402]  190.74 29.45 270 bottom
C517  0.1U/16V_4  [CC0402]  189.72 29.45 270 bottom
C518  4.7U/6.3V_6  [CC0603]  288.53 28.69 0 bottom
C519  1000P/50V_4  [CC0402]  295.77 28.18 180 bottom
C520  0.1U/16V_4  [CC0402]  307.07 28.05 0 bottom
C521  0.1U/25V/X7R_6  [CC0603]  283.19 26.91 180 bottom
C522  0.1U/16V_4  [CC0402]  288.78 27.42 0 bottom
C523  *Clamp-Diode_NC  [CC0402]  306.17 26.42 270 bottom
C524  33P/50V_4  [CC0402]  35.03 42.96 270 bottom
C525  *0.47U/6.3V_4_NC  [CC0402]  145.3 77.71 0 top
C528  0.1U/16V_4  [CC0402]  261.48 27.75 0 top
C529  0.1U/16V_4  [CC0402]  261.48 28.76 0 top
C530  0.1U/16V_4  [CC0402]  259.32 25.51 0 top
C531  0.1U/16V_4  [CC0402]  259.32 26.53 0 top
C532  2.2U/6.3V_6  [CC0603]  247.51 35.93 270 top
C534  0.1U/16V_4  [CC0402]  248.67 36.23 270 top
C535  0.01U/16V_4  [CC0402]  247.19 28.3 0 top
C536  2.2U/6.3V_6  [CC0603]  261.6 35.65 180 top
C537  *10U/6.3V_8_NC  [CC0805]  82.52 31.37 270 bottom
C538  *10U/6.3V_8_NC  [CC0805]  70.96 21.59 0 bottom
C539  1U/6.3V_4  [CC0402]  134.08 88.52 90 top
C540  1U/6.3V_4  [CC0402]  135.86 88.52 90 top
C541  0.1U/16V_4  [CC0402]  264.38 31.11 0 top
C542  0.1U/16V_4  [CC0402]  264.38 29.72 0 top
CN1  TOUCH SCREEN  [GS12203-1011-9F-20P-R]  22.25 101.7 90 bottom
CN2  POWER_JACK  [DCJK-2DC3074-000111F-2P]  1.9 94.2 90 bottom
CN3  HDMI CONN_4 pin GND  [HDMI-2HE1608-000111F-19P-LDV]  326.89 89.7 270 bottom
CN4  USB3.0 CONN  [USB-YBA-USB-032-P01-9P-RUH-SMT]  3.55 59.7 90 bottom
CN5  USB3.0 CONN  [USB-YBA-USB-032-P01-9P-RUH-SMT]  326.45 69.7 270 bottom
CN6  YUSB0012-P001A  [USB-YUSB0012-P001A-10P]  3.55 77.7 90 bottom
CN7  RJ45_CONN  [RJ45-JM361C-HP34AA03-9H-8P]  328.05 49.78 270 bottom
CN8  FPC/FFC_6P_H=2  [88513-0601-6P-L-SMT]  251.26 36.61 180 bottom
CN9  CARDREADER CONN  [SDCARD-CS1M-098-H-N-11P]  5.65 36 90 bottom
CN10  INT SPEAKER CONN  [50281-0060N-001-6P-L-SMT]  303.15 35.45 90 bottom
CN11  7300L30-100000-G4  [GS12301-1011A-9F-30P-L-SMT]  278.75 34.7 0 bottom
CN12  2SJ3061-021111F  [PHJK-2SJ3061-021111F-7P]  327.3 31.7 270 bottom
CN14  APCI0019-P002A  [MIPCI-APCI0019-P002A-75P-KE]  74 34.7 90 bottom
CN15  TOUCH PAD CONN  [50503-0080N-001-8P-L]  187.4 25.05 180 bottom
CN16  50690-0324N-001  [BL135H-32RLA-TAND-32P-L-SMT]  216.82 24.7 180 bottom
CN17  SATA HDD  [SATA-C166G1-12208-L-22P-R]  282.6 22.57 180 bottom
CN18  BP07061-BA015  [50456-00841-001-8P-L]  28.7 6.22 180 bottom
D1  SDMK0340L-7-F  [DSMV]  126.6 116.01 180 top
D2  *Dis@SDM10K45-7-F_NC  [DSM]  186.93 74.26 180 top
D3  *Dis@SDM10K45-7-F_NC  [DSM]  190.43 72.93 270 top
D4  BAT54CW T/R  [UMT_213-3-1_3]  210.9 37.98 0 top
D5  SDMK0340L-7-F  [DSMV]  216.64 36.56 180 top
D7  BAT54CW T/R  [UMT_213-3-1_3]  193.15 19.8 90 top
D8  SDMK0340L-7-F  [DSMV]  172.45 94.6 90 bottom
D9  SDM10K45-7-F  [DSMV]  313.93 94.47 90 bottom
D10  SDM10K45-7-F  [DSMV]  312.02 94.47 90 bottom
D11  SDMK0340L-7-F  [DSMV]  196.32 51.42 180 bottom
D12  SDMK0340L-7-F  [DSMV]  196.32 49.64 0 bottom
D15  SDMK0340L-7-F  [DSMV]  243.19 43.04 90 bottom
D17  BAT54CW T/R  [UMT_213-3-1_3]  275.19 28.31 180 top
D18  BAT54CW T/R  [UMT_213-3-1_3]  275.34 43.34 180 bottom
D19  SDMK0340L-7-F  [DSMV]  288.91 37.78 0 bottom
D20  SDMK0340L-7-F  [DSMV]  240.14 37.32 0 bottom
D21  SDMK0340L-7-F  [DSMV]  212.45 31.48 180 bottom
D22  *BAT54CW_NC  [UMT_213-3-1_3]  279.38 39.86 270 bottom
EC1  0.1U/25V_4  [CC0402]  148.57 118.48 90 top
EC2  1000P/50V_4  [CC0402]  14.57 92.68 90 top
EC3  2200P/50V_4  [CC0402]  15.59 92.68 90 top
EC4  0.1U/25V_6  [CC0603]  16.73 92.42 90 top
EC5  *10P/50V_4_NC  [CC0402]  216.64 34.78 0 top
EC6  *22P/50V_4_NC  [CC0402]  216.64 32.75 0 top
EC7  0.1U/25V_4  [CC0402]  167.5 32.63 180 top
EC8  *2200P/50V_4_NC  [CC0402]  40.08 28.36 180 top
EC9  *0.1U/25V_6_NC  [CC0603]  40.27 27.22 180 top
EC10  *0.1U/25V_4_NC  [CC0402]  121.62 119.54 180 bottom
EC11  *2200P/50V_4_NC  [CC0402]  121.62 118.52 180 bottom
EC12  2200P/50V_4  [CC0402]  152.71 117.97 90 bottom
EC13  *10P/50V_4_NC  [CC0402]  164.19 90.66 180 bottom
EC14  0.1U/25V_6  [CC0603]  17.35 90.64 0 bottom
EC15  *6.8P/50V/NPO_4_NC  [CC0402]  298.94 58.53 180 bottom
EC16  *6.8P/50V/NPO_4_NC  [CC0402]  298.94 57.26 180 bottom
EC17  *6.8P/50V/NPO_4_NC  [CC0402]  298.94 53.45 180 bottom
EC18  *6.8P/50V/NPO_4_NC  [CC0402]  298.94 52.18 180 bottom
EC19  *6.8P/50V/NPO_4_NC  [CC0402]  298.94 50.79 180 bottom
EC20  *6.8P/50V/NPO_4_NC  [CC0402]  298.94 49.52 180 bottom
EC21  *6.8P/50V/NPO_4_NC  [CC0402]  299.07 45.83 180 bottom
EC22  *6.8P/50V/NPO_4_NC  [CC0402]  299.07 44.56 180 bottom
EC23  2200P/50V_4  [CC0402]  37.72 36.73 0 bottom
EC24  0.1U/25V_6  [CC0603]  37.88 35.53 0 bottom
EC33  1.6P/50V_4  [CC0402]  19.26 59.73 270 top
EC34  1.6P/50V_4  [CC0402]  19.26 61.81 90 top
EC35  1.6P/50V_4  [CC0402]  20.23 77.38 270 top
EC36  1.6P/50V_4  [CC0402]  20.23 79.51 90 top
EC37  1.6P/50V_4  [CC0402]  309.79 67.8 90 top
EC38  1.6P/50V_4  [CC0402]  309.79 65.77 270 top
EL1  EXC24CG900U  [CHOKE-DLP11SN900HL2L-4P-1]  310.62 95.87 0 top
EL2  EXC24CG900U  [CHOKE-DLP11SN900HL2L-4P-1]  310.62 94.22 0 top
EL3  EXC24CG900U  [CHOKE-DLP11SN900HL2L-4P-1]  310.62 92.57 0 top
EL4  EXC24CG900U  [CHOKE-DLP11SN900HL2L-4P-1]  310.62 90.92 0 top
EL5  HCB2012KF800T50  [RC0805]  17.5 92.34 180 bottom
EL6  DLP11SN900HL2L  [CHOKE-DLP11SN900HL2L-4P-1]  306.94 68.95 0 bottom
EL7  DLP11SN900HL2L  [CHOKE-DLP11SN900HL2L-4P-1]  20.68 66.28 90 bottom
EL8  DLP11SN900HL2L  [CHOKE-DLP11SN900HL2L-4P-1]  21.01 55.61 180 bottom
EL13  DLW21HN900HQ2L  [CHOKE-NCCM20C900-TR-4P]  277.86 28.18 270 bottom
EL14  DLW21HN900HQ2L  [CHOKE-NCCM20C900-TR-4P]  275.45 28.18 270 bottom
ESD1  *TVL ST23 04 AD0_NC  [TSOP6-2_8-95]  310.62 70.85 270 bottom
ESD2  *TVL ST23 04 AD0_NC  [TSOP6-2_8-95]  17.89 67.3 90 bottom
ESD3  *TVL ST23 04 AD0_NC  [TSOP6-2_8-95]  17.89 54.85 90 bottom
ESD4  *SRV05-4.TCT_NC  [TSOP6-2_8-95]  294.88 53.45 90 bottom
ESD5  *SRV05-4.TCT_NC  [TSOP6-2_8-95]  295.51 46.98 90 bottom
ESD6  TVL ST23 04 AD0  [TSOP6-2_8-95]  28.18 14.08 180 bottom
EU1  ESD7004MUTAG  [UDFN10-2_5X1-5]  17.76 77.46 90 top
EU2  ESD7004MUTAG  [UDFN10-2_5X1-5]  312.53 69.58 270 top
EU3  ESD7004MUTAG  [UDFN10-2_5X1-5]  17.51 59.8 90 top
FAN1  FAN CONN  [50271-0040N-V01-4P-L]  97.95 54.7 90 bottom
FAN2  FAN CONN  [50271-0040N-V01-4P-L]  239.37 53.4 180 bottom
G1  *SHORT_ PAD1  [SOLDERJUMPER-2]  199.5 27.93 270 top
G2  *0_4_NC  [RC0402]  195.31 18.27 90 bottom
H1  *h-c59d59n  [H-C59D59N]  115.25 126.2 0 top
H2  *h-c59d59n  [H-C59D59N]  214.25 126.2 0 top
H3  *h-tc236bc315d98p2  [H-TC236BC315D98P2]  109.25 126.2 0 top
H4  *h-tc236bc315d98p2  [H-TC236BC315D98P2]  220.25 126.2 0 top
H5  *h-tc315bc150d150pt  [H-TC315BC150D150PT]  186.51 112.69 0 top
H6  *H-TSBC315D98P2  [H-TC236BC315D98P2]  8.25 105.7 0 top
H7  *H-TC394BC315D130P2  [H-TC394BC315D130P2]  311.65 104.2 0 top
H8  *INTEL-BKT-SHARK-ULT  [INTEL-BKT-SHARK-ULT]  140.75 94.5 180 top
H9  *h-tc315i190bc150d150pt  [H-TC315I190BC150D150PT]  200.19 75.11 0 top
H10  *h-tc394bc315d138p2  [H-TC394BC315D138P2]  97.75 64.7 0 top
H11  *h-tc394bc315d138p2  [H-TC394BC315D138P2]  232.75 64.7 0 top
H12  *h-tc236bc315d98p2  [H-TSBC315D98P2]  321.75 21.7 0 top
H13  *h-tc394bc315d138p2  [H-TC394BC315D138P2]  172.25 18.7 0 top
H14  *h-tc276bc315d118p2  [H-TC276BC315D118P2]  18 14.7 0 top
H17  -  [H-TC217BC141D141PT]  45.75 34.7 180 bottom
HDMIF1  1206L110THYR  [F3_2X1_65-2_8]  312.53 87.87 0 bottom
HDMIF2  *0603L025YR_NC  [F1_6X0_8-1_8]  21.4 98.44 180 top
HDMIF3  0603L025YR  [F1_6X0_8-1_8]  20.58 95.95 270 top
HE1  YB8251ST23  [SOT23_213-3_3-2]  18.7 109.5 270 top
JDIM1  DDR3-DIMM1_H=4.0_RVS  [DDR-DDRRK-20401-TP4B-204P-SMT]  147.26 40.7 180 bottom
L1  Dis@HCB1005KF-330T30  [RC0402]  195.18 112.64 270 top
L2  2.2uH_8  [RC0805]  150.48 110.73 0 top
L3  Dis@HCB1005KF-330T30  [RC0402]  204.22 108.14 270 top
L4  *WCM2012B900GBE_NC  [CHOKE-WCM2012-4P]  19.79 106.67 180 top
L5  WCM2012B900GBE  [CHOKE-WCM2012-4P]  19.79 104.89 180 top
L6  FCM1005KF-301T03  [RC0402]  17.89 101.08 180 top
L7  FCM1005KF-301T03  [RC0402]  17.89 99.81 180 top
L8  2.2uH_8  [RC0805]  173.08 93.08 0 top
L9  Dis@BLM15PX181SN1D  [RC0402]  175.88 91.81 90 top
L10  Dis@HCB1005KF-330T30  [RC0402]  178.42 88.76 90 top
L11  2.2uH_8  [RC0805]  145.27 87.87 0 top
L12  BLM15PX181SN1D  [RC0402]  304.15 42.53 180 top
L13  BLM15PX181SN1D  [RC0402]  300.08 40.63 90 top
L14  FCM1005KF-301T03  [RC0402]  315.25 35.8 180 top
L15  FCM1005KF-301T03  [RC0402]  315.96 32.5 90 top
L16  FBM-11-160808-601A10T  [RC0603]  313.93 30.47 90 top
L17  FCM1005KF-700T05  [RC0402]  193.53 28.31 0 top
L18  FCM1005KF-700T05  [RC0402]  193.53 27.04 0 top
L19  2.2uH_8  [RC0805]  154.92 109.71 270 bottom
L20  2.2uH_8  [RC0805]  150.73 109.21 90 bottom
L21  2.2uH_8  [RC0805]  154.62 106.16 90 bottom
L22  4.7uH_680mA_DCR=0.12 @7.96MHz  [L2_5X1_8-1_8-SMT]  284.08 45.96 90 bottom
L23  FCM1005KF-121T05_500mA  [RC0402]  241.03 41.52 180 bottom
L24  BLM15PX181SN1D  [RC0402]  309.1 40.63 0 bottom
L25  FCM1005KF-121T05_500mA  [RC0402]  241.03 40.25 180 bottom
L26  TI160808U600  [RC0603]  293.45 38.77 0 bottom
L27  TI160808U600  [RC0603]  293.35 36.05 0 bottom
L28  TI160808U600  [RC0603]  293.23 33.39 0 bottom
L29  TI160808U600  [RC0603]  293.35 31.74 0 bottom
L30  PBY160808T-151Y-N  [RC0603]  293.35 30.21 180 bottom
L31  PBY160808T-151Y-N  [RC0603]  293.35 28.18 180 bottom
L32  WCM2012B900GBE  [CHOKE-WCM2012-4P]  280.14 28.18 270 bottom
LED1  LED_White  [LEDLTW-C191DS5]  153 126.7 0 top
LED2  LED_White  [LEDLTW-C191DS5]  165 126.7 0 top
LED3  LED_White  [LEDLTW-C191DS5]  177 126.7 0 top
NOREF  -  []  141.58 18.92 0 top
NOREF#2  -  []  154.94 22.17 0 top
NOREF#3  -  []  8.25 105.7 0 top
NOREF#4  -  []  47.86 -46.5 0 top
NOREF#5  -  []  126.27 68.26 0 top
NOREF#6  -  []  220.58 -29.22 0 top
NOREF#7  -  []  129.14 56.25 180 bottom
PC1  *10U/25V_8_NC  [CC0805]  119.87 123.05 270 top
PC2  *10U/25V_8_NC  [CC0805]  121.95 123.05 270 top
PC3  10U/25V_8  [CC0805]  149.72 122.29 0 top
PC4  Dis@1000P/50V_4  [CC0402]  218.93 119.75 270 top
PC5  0.1U/25V_4  [CC0402]  130.26 118.65 0 top
PC6  0.1U/25V_4  [CC0402]  116.7 118.48 270 top
PC7  10U/25V_8  [CC0805]  150.22 117.59 90 top
PC8  0.01U/16V_4  [CC0402]  160.13 117.46 90 top
PC9  Dis@0.1U/10V_4  [CC0402]  217.66 117.21 270 top
PC10  *Dis@10U/6.3V_6_NC  [CC0603]  219.06 117.21 270 top
PC11  Dis@0.1U/10V_4  [CC0402]  224.01 117.08 270 top
PC12  1U/6.3V_4  [CC0402]  172.7 116.7 0 top
PC13  0.1U/16V/X7R_4  [CC0402]  174.94 114.29 180 top
PC14  4700P/25V/X7R  [CC0402]  179.18 117.18 270 top
PC15  Dis@1000P/50V_4  [CC0402]  199.25 110.22 0 top
PC16  *1U/25V_6_NC  [CC0603]  21.48 87.34 0 top
PC17  *0.01U/25V_4_NC  [CC0402]  19.16 82.45 270 top
PC18  Dis@4700P/25V/X7R  [CC0402]  225.53 75.42 270 top
PC19  Dis@0.1U/10V_4  [CC0402]  230.61 71.61 90 top
PC20  *Dis@10U/6.3V_6_NC  [CC0603]  229.34 71.36 90 top
PC21  Dis@0.1U/10V_4  [CC0402]  224.9 68.69 270 top
PC22  0.1U/10V_4  [CC0402]  211.72 68.03 90 top
PC23  330u_2.5V_7343_h=1.4  [CC7343-2_15H]  208.75 66.15 90 top
PC24  330u_2.5V_7343_h=1.4  [CC7343-2_15H]  203.9 66.14 90 top
PC25  *330u_2.5V_7343_h=1.4_NC  [CC7343-2_15H]  199.09 62.61 270 top
PC26  1U/25V_6  [CC0603]  235.58 57.37 270 top
PC27  0.1U/16V/X7R_4  [CC0402]  236.99 57.07 270 top
PC28  0.22U/25V_6  [CC0603]  229.99 54.88 270 top
PC29  10P/50V_4  [CC0402]  238.23 54.72 90 top
PC30  100p/50V_4  [CC0402]  239.76 54.22 0 top
PC31  4.7U/6.3V_6  [CC0603]  229.08 52.89 180 top
PC32  47P/50V_4  [CC0402]  242.53 52.69 270 top
PC33  0.01U/50V_4  [CC0402]  238.73 52.18 180 top
PC34  2700P/50V_4  [CC0402]  238.23 50.64 90 top
PC35  0.22U/25V_6  [CC0603]  229.97 50.44 90 top
PC36  0.1U/16V/X7R_4  [CC0402]  189.21 42.66 90 top
PC37  0.01U/16V_4  [CC0402]  193.53 40.95 270 top
PC38  1U/6.3V_4  [CC0402]  279.26 41.52 0 top
PC39  0.01U/16V_4  [CC0402]  279.26 40.5 0 top
PC40  0.1U/25V_6  [CC0603]  50.27 37.2 270 top
PC41  0.1U/25V_6  [CC0603]  49 37.2 270 top
PC42  1000P/50V_4  [CC0402]  284.97 38.98 180 top
PC43  0.1U/25V_4  [CC0402]  279.26 38.47 0 top
PC44  0.1U/16V_4  [CC0402]  49.89 34.66 180 top
PC46  0.1U/16V/X7R_4  [CC0402]  193.45 34.71 90 top
PC47  0.01U/25V_4  [CC0402]  52.18 31.61 0 top
PC48  1U/10V_6  [CC0603]  39.86 30.21 90 top
PC50  *0.1U/10V_4_NC  [CC0402]  120.29 33.17 180 top
PC51  4700P/25V/X7R  [CC0402]  189.21 32.88 0 top
PC52  1U/6.3V_4  [CC0402]  132.73 32.53 90 top
PC53  0.1U/10V_4  [CC0402]  172.22 31.9 270 top
PC54  0.047U/25V_4  [CC0402]  43.62 27.11 0 top
PC55  *22P/50V_4_NC  [CC0402]  175.12 31.36 0 top
PC56  1000P/50V_4  [CC0402]  35.36 31.17 0 top
PC57  100P/50V_4  [CC0402]  51.56 27.07 180 top
PC58  0.01U/25V_4  [CC0402]  51.56 26.05 0 top
PC59  1U/6.3V_4  [CC0402]  168.41 29.1 0 top
PC60  4.7U/6.3V_6  [CC0603]  124.75 28.6 0 top
PC61  0.1U/16V_4  [CC0402]  47.01 24.96 180 top
PC62  0.033U/10V_4  [CC0402]  177.28 28.21 0 top
PC63  1U/6.3V_4  [CC0402]  168.41 27.96 0 top
PC64  1U/25V_6  [CC0603]  45.41 24.17 90 top
PC65  0.1U/25V_4  [CC0402]  137.04 27.2 0 top
PC66  0.1U/10V_4  [CC0402]  145.69 26.82 180 top
PC67  0.1U/16V/X7R_4  [CC0402]  236.84 26.17 90 top
PC68  10U/6.3V_8  [CC0805]  177.23 25.93 270 top
PC69  0.1U/25V_4  [CC0402]  125.08 25.88 0 top
PC70  1U/16V_4  [CC0402]  203.31 25.64 270 top
PC71  10U/6.3V_8  [CC0805]  179.31 25.4 270 top
PC72  4.7U/6.3V_6  [CC0603]  134.61 24.4 180 top
PC73  0.47U/25V_6  [CC0603]  198.99 24.24 180 top
PC74  0.1U/25V_4  [CC0402]  132.27 24.02 0 top
PC75  0.1U/25V_6  [CC0603]  45.96 21.45 90 top
PC76  0.1U/25V_6  [CC0603]  47.73 21.45 90 top
PC77  *0.1U/50V_6_NC  [CC0603]  178.7 23.01 180 top
PC78  1U/35V_6  [CC0603]  198.99 22.97 0 top
PC79  *Dis@1U/10V_4_NC  [CC0402]  87.36 22.85 270 top
PC80  0.1U/25V_4  [CC0402]  198.99 21.7 0 top
PC81  0.1U/25V_4  [CC0402]  198.99 20.56 180 top
PC82  4700P/25V/X7R  [CC0402]  234.93 19.47 270 top
PC83  0.1U/10V_4  [CC0402]  176.26 125.21 0 bottom
PC84  4.7U/6.3V_6  [CC0603]  207.75 125.08 90 bottom
PC85  *2.2U/10V_6_NC  [CC0603]  126.6 125 180 bottom
PC86  22U/6.3V_6  [CC0603]  160.38 124.95 270 bottom
PC87  22U/6.3V_6  [CC0603]  159.11 124.95 270 bottom
PC88  0.1U/25V_4  [CC0402]  161.53 124.83 270 bottom
PC89  *22P/50V_4_NC  [CC0402]  168.18 124.8 90 bottom
PC90  *0.1U/25V_4_NC  [CC0402]  118.91 124.67 0 bottom
PC91  0.047U/25V_4  [CC0402]  165.39 124.41 180 bottom
PC92  2200P/50V_4  [CC0402]  198.83 123.54 90 bottom
PC93  0.1U/25V_4  [CC0402]  200.03 125.59 270 top
PC94  0.1U/25V_4  [CC0402]  203.91 123.31 90 bottom
PC95  1000P/50V_4  [CC0402]  145.4 123.3 270 bottom
PC96  4.7U/25V_8  [CC0805]  202.39 123.08 90 bottom
PC97  *4.7U/25V_8_NC  [CC0805]  200.36 123.08 90 bottom
PC98  0.1U/25V_4  [CC0402]  205.11 122.92 270 bottom
PC99  15U/25V  [ECAP6D3S]  154.92 122.9 270 bottom
PC100  330UF,6.3*4.2L,ESR=16  [ECAP6_3X5_8-7_2]  181.11 122.69 270 bottom
PC101  10U/25V_8  [CC0805]  150.48 122.54 270 bottom
PC102  0.1U/10V_4  [CC0402]  210.4 122.36 270 bottom
PC103  1U/6.3V_4  [CC0402]  169.98 122.12 180 bottom
PC104  *2200P/50V_4_NC  [CC0402]  197.29 122.01 180 bottom
PC105  1U/6.3V_4  [CC0402]  111.85 120.33 270 bottom
PC106  0.1U/25V_4  [CC0402]  167.62 120.13 0 bottom
PC107  0.33U/6.3V_4  [CC0402]  110.8 120.08 270 bottom
PC108  1500P/50V_4  [CC0402]  107.09 119.77 180 bottom
PC109  *100P/50V_4_NC  [CC0402]  109.13 119.59 0 bottom
PC110  10U/6.3V_6  [CC0603]  167.6 119.02 0 bottom
PC111  *1000P/50V_4_NC  [CC0402]  124.19 118.73 90 bottom
PC112  *10U/25V_8_NC  [CC0805]  119.46 118.63 90 bottom
PC113  1U/6.3V_4  [CC0402]  115.47 117.2 180 bottom
PC114  0.1U/25V_4  [CC0402]  150.71 116.8 180 bottom
PC115  2.2U/10V_6  [CC0603]  144 115.81 90 bottom
PC116  22U/6.3V_6  [CC0603]  130.24 116.24 0 bottom
PC117  22U/6.3V_6  [CC0603]  139.6 116.11 180 bottom
PC118  *0.068UF/16V_4_NC  [CC0402]  107.55 116.11 90 bottom
PC119  *0.1U/16V_4_NC  [CC0402]  106.33 116.14 90 bottom
PC120  22U/6.3V_6  [CC0603]  142.66 115.4 270 bottom
PC121  22U/6.3V_6  [CC0603]  141.49 115.4 270 bottom
PC122  22U/6.3V_6  [CC0603]  128.36 115.53 270 bottom
PC123  22U/6.3V_6  [CC0603]  127.16 115.53 270 bottom
PC124  *Dis@10U/6.3V_6_NC  [CC0603]  204.45 114.29 180 bottom
PC125  0.068UF/16V_4  [CC0402]  107.6 113.91 270 bottom
PC126  0.1U/16V_4  [CC0402]  106.54 113.91 270 bottom
PC127  Dis@0.1U/10V_4  [CC0402]  192.39 113.65 90 bottom
PC128  Dis@0.1U/10V_4  [CC0402]  204.33 112.89 180 bottom
PC129  22U/6.3V_6  [CC0603]  138.03 112.89 90 bottom
PC130  22U/6.3V_6  [CC0603]  136.76 112.89 90 bottom
PC131  22U/6.3V_6  [CC0603]  135.49 112.89 90 bottom
PC132  *22U/6.3V_6_NC  [CC0603]  134.22 112.89 90 bottom
PC133  *22U/6.3V_6_NC  [CC0603]  132.95 112.89 90 bottom
PC134  *22U/6.3V_6_NC  [CC0603]  131.68 112.89 90 bottom
PC135  22U/6.3V_6  [CC0603]  130.41 112.89 90 bottom
PC136  4700P/25V/X7R  [CC0402]  109.84 111.75 90 bottom
PC137  1000PF/50V_4  [CC0402]  108.82 111.75 90 bottom
PC138  0.47U/25V_8  [CC0805]  20.19 91.63 90 bottom
PC139  0.01U/25V_4  [CC0402]  17.25 84.57 0 bottom
PC140  0.1U/25V_6  [CC0603]  17.64 83.43 0 bottom
PC141  15U/25V  [ECAP6D3S]  102.47 73.27 90 bottom
PC142  560U_2V_7343_2  [CC7343-2_15H]  199.83 62.61 270 bottom
PC143  0.1U/10V_4  [CC0402]  196.91 61.84 270 bottom
PC144  1U/25V_6  [CC0603]  33.76 59.17 270 bottom
PC149  15U/25V  [ECAP6D3S]  40.11 50.28 180 bottom
PC150  2200P/50V_4  [CC0402]  228.51 50.79 180 bottom
PC152  4.7U/25V/X6S_8  [CC0805]  223.51 50.55 180 bottom
PC153  2200P/50V_4  [CC0402]  200.64 50.15 270 bottom
PC154  4.7U/25V_8  [CC0805]  220.78 49.84 90 bottom
PC155  4.7U/25V_8  [CC0805]  218.77 49.84 90 bottom
PC157  2200P/50V_4  [CC0402]  216.64 49.26 0 bottom
PC158  *Dis@0.22U/6.3V_4_NC  [CC0402]  259.32 48.12 90 top
PC159  4.7U/25V/X6S_8  [CC0805]  206.84 48.53 0 bottom
PC160  0.1U/25V_4  [CC0402]  216.64 48.25 180 bottom
PC161  2200P/50V_4  [CC0402]  214.36 48.12 270 bottom
PC162  0.1U/25V_4  [CC0402]  213.22 48.12 90 bottom
PC164  4.7U/25V/X6S_8  [CC0805]  211.56 47.86 90 bottom
PC165  4.7U/25V/X6S_8  [CC0805]  209.55 47.86 90 bottom
PC166  1000P/50V_4  [CC0402]  239.15 46.73 90 bottom
PC167  0.1U/25V_4  [CC0402]  283.95 43.04 0 bottom
PC168  15U/25V  [ECAP6D3S]  213.85 42.71 0 bottom
PC169  10U/25V_8  [CC0805]  37.31 40.47 0 bottom
PC170  10U/25V_8  [CC0805]  37.3 38.42 0 bottom
PC171  0.01U/25V_4  [CC0402]  242.78 36.03 270 bottom
PC172  220U/6.3V_6.3X4.2  [ECAP6D3S]  116.85 29.32 180 bottom
PC173  330u_2.5V_7343_h=1.9  [CC7343-2_15H]  166.89 28.21 270 bottom
PC174  0.1U/10V_4  [CC0402]  163.97 27.85 90 bottom
PC175  220U/6.3V_6.3X4.2  [ECAP6D3S]  144.67 26.73 0 bottom
PC176  0.1U/10V_4  [CC0402]  109.69 26.02 180 bottom
